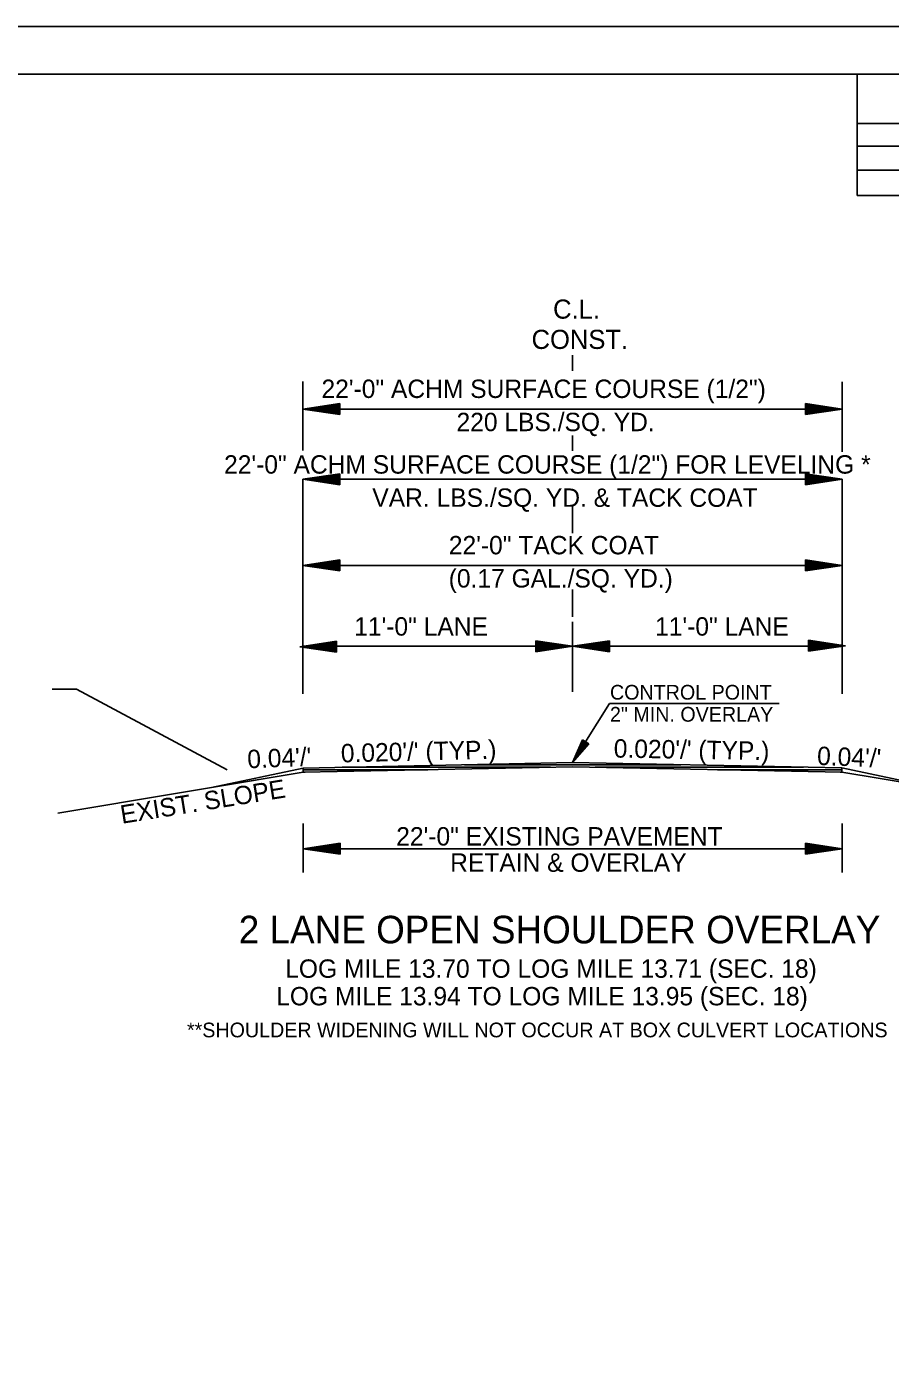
# Model space of a CAD drawing. Extents: x 2263886 to 2266026, y -3122850 to -3121850.
# Drawn here: x 2265448.3 to 2265483.5, y -3122391.3 to -3122337.2 of the extents above; entities that cross this region are included whole.
import ezdxf

# ---------------------------------------------------------------- set-up
doc = ezdxf.new("R2010")
doc.units = 0
for name, color, linetype in [('_CIVIL_CONSTRUCTION', 7, 'Continuous'), ('Default', 7, 'Continuous'), ('R_Border Prem', 7, 'Continuous'), ('R_Draft', 7, 'Continuous')]:
    doc.layers.add(name, color=color, linetype=linetype)

msp = doc.modelspace()

# ---------------------------------------------------------------- linework, layer by layer
at = {"layer": '_CIVIL_CONSTRUCTION'}
msp.add_line((2265359.025, -3122337.151), (2265525.692, -3122337.151), dxfattribs=at)
for points in [[(2265359.022, -3122337.151), (2265525.692, -3122337.151), (2265525.692, -3122443.82), (2265359.022, -3122443.82)], [(2265482.186, -3122339.098), (2265482.186, -3122344.038), (2265500.052, -3122344.038), (2265500.052, -3122345.498), (2265511.651, -3122345.498), (2265511.651, -3122357.664), (2265523.316, -3122357.664), (2265523.316, -3122441.828), (2265365.226, -3122441.828), (2265365.226, -3122339.098)]]:
    msp.add_lwpolyline(points, close=True, dxfattribs=at)
at = {"layer": 'Default'}
for p, q in [((2265464.67, -3122367.473), (2265459.591, -3122367.473)), ((2265459.671, -3122367.573), (2265459.593, -3122367.573)), ((2265469.669, -3122367.373), (2265461.169, -3122367.373)), ((2265474.986, -3122367.273), (2265466.168, -3122367.273)), ((2265479.988, -3122367.373), (2265471.489, -3122367.373)), ((2265481.554, -3122367.473), (2265476.488, -3122367.473)), ((2265481.552, -3122367.573), (2265481.487, -3122367.573))]:
    msp.add_line(p, q, dxfattribs=at)
at = {"layer": 'R_Border Prem'}
for p, q in [((2265470.573, -3122351.193), (2265470.573, -3122350.566)), ((2265459.573, -3122351.635), (2265459.573, -3122354.452)), ((2265461.073, -3122352.536), (2265459.573, -3122352.761)), ((2265461.073, -3122352.986), (2265459.573, -3122352.761)), ((2265459.573, -3122352.761), (2265481.573, -3122352.761)), ((2265461.073, -3122352.573), (2265459.823, -3122352.761)), ((2265461.073, -3122352.948), (2265459.823, -3122352.761)), ((2265461.073, -3122352.611), (2265460.081, -3122352.761)), ((2265461.073, -3122352.91), (2265460.081, -3122352.761)), ((2265461.073, -3122352.649), (2265460.331, -3122352.761)), ((2265461.073, -3122352.872), (2265460.331, -3122352.761)), ((2265461.073, -3122352.687), (2265460.585, -3122352.761)), ((2265461.073, -3122352.833), (2265460.585, -3122352.761)), ((2265461.073, -3122352.725), (2265460.836, -3122352.761)), ((2265461.073, -3122352.796), (2265460.836, -3122352.761)), ((2265461.073, -3122352.986), (2265461.073, -3122352.536)), ((2265480.073, -3122352.536), (2265481.573, -3122352.761)), ((2265480.073, -3122352.536), (2265480.073, -3122352.986)), ((2265480.073, -3122352.573), (2265481.322, -3122352.761)), ((2265480.073, -3122352.611), (2265481.064, -3122352.761)), ((2265480.073, -3122352.649), (2265480.815, -3122352.761)), ((2265480.073, -3122352.688), (2265480.56, -3122352.761)), ((2265480.073, -3122352.725), (2265480.31, -3122352.761)), ((2265480.073, -3122352.986), (2265481.573, -3122352.761)), ((2265480.073, -3122352.834), (2265480.56, -3122352.761)), ((2265480.073, -3122352.91), (2265481.064, -3122352.761)), ((2265480.073, -3122352.948), (2265481.322, -3122352.761)), ((2265480.073, -3122352.872), (2265480.815, -3122352.761)), ((2265480.073, -3122352.796), (2265480.31, -3122352.761)), ((2265470.573, -3122354.465), (2265470.573, -3122353.841)), ((2265461.073, -3122355.398), (2265459.573, -3122355.623)), ((2265461.073, -3122355.848), (2265459.573, -3122355.623)), ((2265459.573, -3122355.623), (2265459.573, -3122364.377)), ((2265459.573, -3122355.623), (2265481.573, -3122355.623)), ((2265461.073, -3122355.435), (2265459.823, -3122355.623)), ((2265461.073, -3122355.81), (2265459.823, -3122355.623)), ((2265461.073, -3122355.473), (2265460.081, -3122355.623)), ((2265461.073, -3122355.772), (2265460.081, -3122355.623)), ((2265461.073, -3122355.511), (2265460.331, -3122355.623)), ((2265461.073, -3122355.734), (2265460.331, -3122355.623)), ((2265461.073, -3122355.549), (2265460.585, -3122355.623)), ((2265461.073, -3122355.695), (2265460.585, -3122355.623)), ((2265461.073, -3122355.587), (2265460.836, -3122355.623)), ((2265461.073, -3122355.658), (2265460.836, -3122355.623)), ((2265461.073, -3122355.848), (2265461.073, -3122355.398)), ((2265480.073, -3122355.398), (2265481.573, -3122355.623)), ((2265480.073, -3122355.398), (2265480.073, -3122355.848)), ((2265480.073, -3122355.435), (2265481.322, -3122355.623)), ((2265480.073, -3122355.473), (2265481.064, -3122355.623)), ((2265480.073, -3122355.511), (2265480.815, -3122355.623)), ((2265480.073, -3122355.55), (2265480.56, -3122355.623)), ((2265480.073, -3122355.587), (2265480.31, -3122355.623)), ((2265480.073, -3122355.848), (2265481.573, -3122355.623)), ((2265480.073, -3122355.696), (2265480.56, -3122355.623)), ((2265480.073, -3122355.772), (2265481.064, -3122355.623)), ((2265480.073, -3122355.81), (2265481.322, -3122355.623)), ((2265480.073, -3122355.734), (2265480.815, -3122355.623)), ((2265480.073, -3122355.658), (2265480.31, -3122355.623)), ((2265470.573, -3122357.819), (2265470.573, -3122356.717)), ((2265461.073, -3122358.916), (2265459.573, -3122359.141)), ((2265461.073, -3122358.953), (2265459.823, -3122359.141)), ((2265461.073, -3122358.991), (2265460.081, -3122359.141)), ((2265461.073, -3122359.366), (2265461.073, -3122358.916)), ((2265480.073, -3122358.916), (2265481.573, -3122359.141)), ((2265480.073, -3122358.916), (2265480.073, -3122359.366)), ((2265480.073, -3122358.953), (2265481.322, -3122359.141)), ((2265480.073, -3122358.991), (2265481.064, -3122359.141)), ((2265461.073, -3122359.366), (2265459.573, -3122359.141)), ((2265459.573, -3122359.141), (2265481.573, -3122359.141)), ((2265461.073, -3122359.328), (2265459.823, -3122359.141)), ((2265461.073, -3122359.29), (2265460.081, -3122359.141)), ((2265461.073, -3122359.029), (2265460.331, -3122359.141)), ((2265461.073, -3122359.252), (2265460.331, -3122359.141)), ((2265461.073, -3122359.067), (2265460.585, -3122359.141)), ((2265461.073, -3122359.213), (2265460.585, -3122359.141)), ((2265461.073, -3122359.105), (2265460.836, -3122359.141)), ((2265461.073, -3122359.176), (2265460.836, -3122359.141)), ((2265480.073, -3122359.029), (2265480.815, -3122359.141)), ((2265480.073, -3122359.068), (2265480.56, -3122359.141)), ((2265480.073, -3122359.105), (2265480.31, -3122359.141)), ((2265480.073, -3122359.366), (2265481.573, -3122359.141)), ((2265480.073, -3122359.214), (2265480.56, -3122359.141)), ((2265480.073, -3122359.29), (2265481.064, -3122359.141)), ((2265480.073, -3122359.328), (2265481.322, -3122359.141)), ((2265480.073, -3122359.252), (2265480.815, -3122359.141)), ((2265480.073, -3122359.176), (2265480.31, -3122359.141)), ((2265470.573, -3122361.235), (2265470.573, -3122360.118)), ((2265470.573, -3122364.302), (2265470.573, -3122361.447)), ((2265460.947, -3122362.23), (2265459.447, -3122362.455)), ((2265460.947, -3122362.68), (2265460.947, -3122362.23)), ((2265469.073, -3122362.211), (2265470.573, -3122362.436)), ((2265469.073, -3122362.211), (2265469.073, -3122362.661)), ((2265469.073, -3122362.249), (2265470.322, -3122362.436)), ((2265472.073, -3122362.211), (2265470.573, -3122362.436)), ((2265472.073, -3122362.249), (2265470.823, -3122362.436)), ((2265472.073, -3122362.661), (2265472.073, -3122362.211)), ((2265480.198, -3122362.192), (2265481.698, -3122362.417)), ((2265480.198, -3122362.192), (2265480.198, -3122362.642)), ((2265480.198, -3122362.23), (2265481.448, -3122362.417)), ((2265460.947, -3122362.68), (2265459.447, -3122362.455)), ((2265460.573, -3122362.436), (2265459.573, -3122362.436)), ((2265460.947, -3122362.267), (2265459.698, -3122362.455)), ((2265460.947, -3122362.642), (2265459.698, -3122362.455)), ((2265460.947, -3122362.306), (2265459.956, -3122362.455)), ((2265460.947, -3122362.604), (2265459.956, -3122362.455)), ((2265460.947, -3122362.343), (2265460.206, -3122362.455)), ((2265460.947, -3122362.567), (2265460.206, -3122362.455)), ((2265460.947, -3122362.381), (2265460.46, -3122362.455)), ((2265460.947, -3122362.528), (2265460.46, -3122362.455)), ((2265460.573, -3122362.436), (2265470.573, -3122362.436)), ((2265460.947, -3122362.42), (2265460.71, -3122362.455)), ((2265460.947, -3122362.49), (2265460.71, -3122362.455)), ((2265469.073, -3122362.287), (2265470.064, -3122362.436)), ((2265469.073, -3122362.324), (2265469.815, -3122362.436)), ((2265469.073, -3122362.363), (2265469.56, -3122362.436)), ((2265469.073, -3122362.401), (2265469.31, -3122362.436)), ((2265469.073, -3122362.661), (2265470.573, -3122362.436)), ((2265469.073, -3122362.51), (2265469.56, -3122362.436)), ((2265469.073, -3122362.585), (2265470.064, -3122362.436)), ((2265469.073, -3122362.624), (2265470.322, -3122362.436)), ((2265469.073, -3122362.548), (2265469.815, -3122362.436)), ((2265469.073, -3122362.471), (2265469.31, -3122362.436)), ((2265472.073, -3122362.661), (2265470.573, -3122362.436)), ((2265470.573, -3122362.436), (2265481.573, -3122362.436)), ((2265472.073, -3122362.624), (2265470.823, -3122362.436)), ((2265472.073, -3122362.287), (2265471.081, -3122362.436)), ((2265472.073, -3122362.585), (2265471.081, -3122362.436)), ((2265472.073, -3122362.324), (2265471.331, -3122362.436)), ((2265472.073, -3122362.548), (2265471.331, -3122362.436)), ((2265472.073, -3122362.363), (2265471.585, -3122362.436)), ((2265472.073, -3122362.509), (2265471.585, -3122362.436)), ((2265472.073, -3122362.401), (2265471.836, -3122362.436)), ((2265472.073, -3122362.471), (2265471.836, -3122362.436)), ((2265480.198, -3122362.268), (2265481.19, -3122362.417)), ((2265480.198, -3122362.306), (2265480.94, -3122362.417)), ((2265480.198, -3122362.345), (2265480.686, -3122362.417)), ((2265480.198, -3122362.382), (2265480.435, -3122362.417)), ((2265480.198, -3122362.642), (2265481.698, -3122362.417)), ((2265480.198, -3122362.491), (2265480.686, -3122362.417)), ((2265480.198, -3122362.567), (2265481.19, -3122362.417)), ((2265480.198, -3122362.605), (2265481.448, -3122362.417)), ((2265480.198, -3122362.529), (2265480.94, -3122362.417)), ((2265480.198, -3122362.453), (2265480.435, -3122362.417)), ((2265470.575, -3122367.185), (2265472.073, -3122364.767)), ((2265472.073, -3122364.767), (2265478.996, -3122364.767)), ((2265470.974, -3122366.256), (2265470.575, -3122367.185)), ((2265471.229, -3122366.413), (2265470.575, -3122367.185)), ((2265470.995, -3122366.269), (2265470.663, -3122367.043)), ((2265471.208, -3122366.4), (2265470.663, -3122367.043)), ((2265471.017, -3122366.282), (2265470.754, -3122366.897)), ((2265471.186, -3122366.387), (2265470.754, -3122366.897)), ((2265471.038, -3122366.295), (2265470.841, -3122366.755)), ((2265471.165, -3122366.374), (2265470.841, -3122366.755)), ((2265471.06, -3122366.309), (2265470.93, -3122366.611)), ((2265471.142, -3122366.36), (2265470.93, -3122366.611)), ((2265471.229, -3122366.413), (2265470.974, -3122366.256)), ((2265471.081, -3122366.322), (2265471.018, -3122366.469)), ((2265471.121, -3122366.347), (2265471.018, -3122366.469)), ((2265459.59, -3122367.575), (2265449.583, -3122369.242)), ((2265459.59, -3122367.405), (2265455.841, -3122368.199)), ((2265455.841, -3122368.199), (2265459.59, -3122367.575)), ((2265459.59, -3122367.405), (2265470.575, -3122367.185)), ((2265459.59, -3122367.575), (2265459.59, -3122367.405)), ((2265459.59, -3122367.575), (2265459.59, -3122367.405)), ((2265459.59, -3122367.575), (2265459.59, -3122367.405)), ((2265459.59, -3122367.575), (2265459.59, -3122367.575)), ((2265459.593, -3122367.575), (2265470.579, -3122367.355)), ((2265470.575, -3122367.185), (2265481.556, -3122367.404)), ((2265470.579, -3122367.355), (2265481.552, -3122367.574)), ((2265481.556, -3122367.404), (2265481.556, -3122367.574)), ((2265485.48, -3122368.228), (2265481.556, -3122367.404)), ((2265491.562, -3122369.242), (2265481.556, -3122367.574)), ((2265481.556, -3122367.574), (2265481.556, -3122367.574)), ((2265481.556, -3122367.574), (2265485.48, -3122368.228)), ((2265459.59, -3122369.675), (2265459.59, -3122371.675)), ((2265481.569, -3122369.675), (2265481.569, -3122371.675)), ((2265461.09, -3122370.475), (2265459.59, -3122370.7)), ((2265461.09, -3122370.925), (2265459.59, -3122370.7)), ((2265459.59, -3122370.7), (2265481.569, -3122370.7)), ((2265461.09, -3122370.512), (2265459.84, -3122370.7)), ((2265461.09, -3122370.887), (2265459.84, -3122370.7)), ((2265461.09, -3122370.551), (2265460.098, -3122370.7)), ((2265461.09, -3122370.849), (2265460.098, -3122370.7)), ((2265461.09, -3122370.588), (2265460.348, -3122370.7)), ((2265461.09, -3122370.812), (2265460.348, -3122370.7)), ((2265461.09, -3122370.626), (2265460.602, -3122370.7)), ((2265461.09, -3122370.773), (2265460.602, -3122370.7)), ((2265461.09, -3122370.665), (2265460.853, -3122370.7)), ((2265461.09, -3122370.735), (2265460.853, -3122370.7)), ((2265461.09, -3122370.925), (2265461.09, -3122370.475)), ((2265480.069, -3122370.475), (2265481.569, -3122370.7)), ((2265480.069, -3122370.475), (2265480.069, -3122370.925)), ((2265480.069, -3122370.512), (2265481.318, -3122370.7)), ((2265480.069, -3122370.551), (2265481.06, -3122370.7)), ((2265480.069, -3122370.588), (2265480.81, -3122370.7)), ((2265480.069, -3122370.627), (2265480.556, -3122370.7)), ((2265480.069, -3122370.665), (2265480.306, -3122370.7)), ((2265480.069, -3122370.925), (2265481.569, -3122370.7)), ((2265480.069, -3122370.773), (2265480.556, -3122370.7)), ((2265480.069, -3122370.849), (2265481.06, -3122370.7)), ((2265480.069, -3122370.887), (2265481.318, -3122370.7)), ((2265480.069, -3122370.812), (2265480.81, -3122370.7)), ((2265480.069, -3122370.735), (2265480.306, -3122370.7))]:
    msp.add_line(p, q, dxfattribs=at)
for points in [[(2265481.573, -3122351.653), (2265481.573, -3122354.507)], [(2265481.573, -3122355.623), (2265481.573, -3122364.379)], [(2265449.34, -3122364.182), (2265450.34, -3122364.182), (2265456.488, -3122367.473)]]:
    msp.add_lwpolyline(points, dxfattribs=at)
at = {"layer": 'R_Draft'}
for p, q in [((2265365.226, -3122339.098), (2265523.316, -3122339.098)), ((2265482.186, -3122344.038), (2265482.186, -3122339.098)), ((2265482.186, -3122341.108), (2265501.766, -3122341.108)), ((2265482.186, -3122342.038), (2265501.766, -3122342.038)), ((2265482.186, -3122344.038), (2265482.186, -3122343.008)), ((2265482.186, -3122343.008), (2265501.766, -3122343.008)), ((2265523.316, -3122344.038), (2265482.186, -3122344.038))]:
    msp.add_line(p, q, dxfattribs=at)

# ---------------------------------------------------------------- texts
at = {"layer": 'R_Border Prem'}
for s, height, p in [('C.L.', 0.78, (2265469.777, -3122349.069)), ('CONST.', 0.78, (2265468.899, -3122350.305)), ('22\'-0" ACHM SURFACE COURSE (1/2")', 0.75, (2265460.332, -3122352.306)), ('220 LBS./SQ. YD. ', 0.75, (2265465.839, -3122353.661)), ('22\'-0" ACHM SURFACE COURSE (1/2") FOR LEVELING *', 0.75, (2265456.358, -3122355.393)), ('VAR. LBS./SQ. YD. & TACK COAT', 0.75, (2265462.405, -3122356.748)), ('22\'-0" TACK COAT', 0.75, (2265465.526, -3122358.686)), ('(0.17 GAL./SQ. YD.)', 0.75, (2265465.52, -3122360.041)), ('11\'-0" LANE', 0.75, (2265461.666, -3122362.003)), ('11\'-0" LANE', 0.75, (2265473.938, -3122362.003)), ('CONTROL POINT', 0.6, (2265472.098, -3122364.614)), ('2" MIN. OVERLAY', 0.6, (2265472.098, -3122365.514)), ('22\'-0" EXISTING PAVEMENT', 0.75, (2265463.38, -3122370.568)), ('RETAIN & OVERLAY', 0.75, (2265465.58, -3122371.64)), ('2 LANE OPEN SHOULDER OVERLAY', 1.125, (2265456.957, -3122374.56)), ('LOG MILE 13.70 TO LOG MILE 13.71 (SEC. 18)', 0.75, (2265458.851, -3122375.965)), ('LOG MILE 13.94 TO LOG MILE 13.95 (SEC. 18)', 0.75, (2265458.485, -3122377.09)), ('**SHOULDER WIDENING WILL NOT OCCUR AT BOX CULVERT LOCATIONS', 0.6, (2265454.845, -3122378.394))]:
    msp.add_text(s, height=height, dxfattribs=at).set_placement(p)
for s, rotation, p in [("0.04'/'", 2.2906, (2265457.32, -3122367.419)), ("0.020'/' (TYP.)", 1.4254, (2265461.13, -3122367.179)), ("0.020'/' (TYP.)", 359.0628, (2265472.247, -3122366.978)), ("0.04'/'", 357.7094, (2265480.534, -3122367.276)), ('EXIST. SLOPE', 9.1534, (2265452.192, -3122369.683))]:
    msp.add_text(s, height=0.75, rotation=rotation, dxfattribs=at).set_placement(p)

doc.saveas('drawing.dxf')
